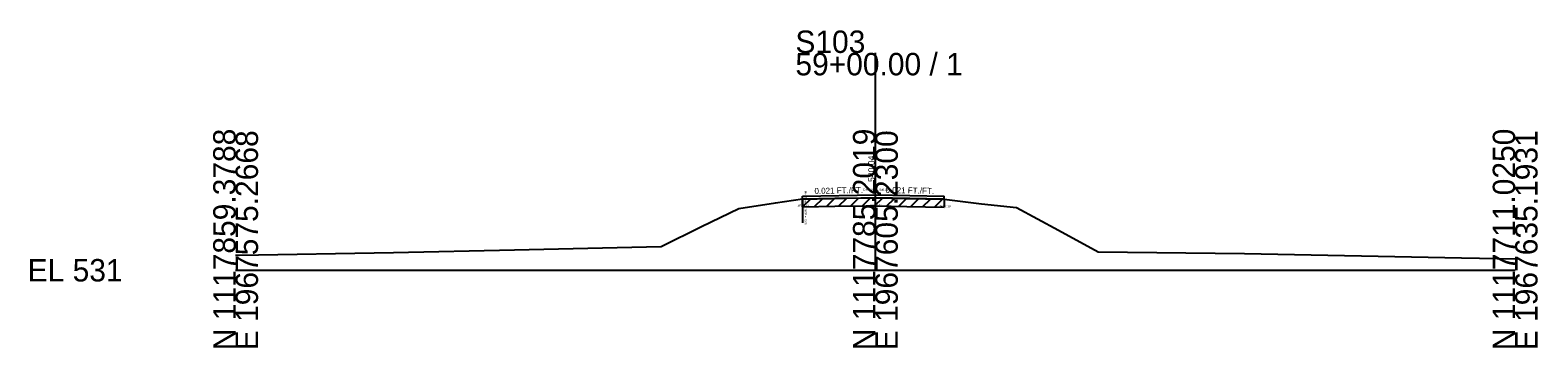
# Model space of a CAD drawing. Extents: x -26 to 163, y -10 to 24018.
# Drawn here: x -25.7 to 162.8, y 8490.3 to 8530 of the extents above; entities that cross this region are included whole.
import ezdxf

# ---------------------------------------------------------------- set-up
doc = ezdxf.new("R2010")
doc.units = 0
for name, color, linetype in [('RD_GPK_XS_Cell', 7, 'Continuous'), ('RD_XS_ExGround', 7, 'Continuous'), ('RD_XS_ExPaveRet', 7, 'Continuous'), ('RD_XS_Misc_Line', 7, 'Continuous'), ('RD_XS_PaveOvlay_CP', 7, 'Continuous'), ('RD_XS_TX_Elev_EX', 7, 'Continuous'), ('RD_XS_TX_ExEOP', 7, 'Continuous'), ('RD_XS_TX_Notes', 7, 'Continuous'), ('RD_XS_TX_Profile', 7, 'Continuous'), ('RD_XS_TX_Slope', 7, 'Continuous')]:
    doc.layers.add(name, color=color, linetype=linetype)

msp = doc.modelspace()

# ---------------------------------------------------------------- linework, layer by layer
at = {"layer": 'RD_GPK_XS_Cell'}
for p, q in [((80, 8500), (80, 8527.15)), ((0, 8500), (80, 8500)), ((80, 8500), (160, 8500))]:
    msp.add_line(p, q, dxfattribs=at)
at = {"layer": 'RD_XS_ExGround'}
msp.add_lwpolyline([(0, 8501.9), (0.46, 8501.89), (19.76, 8502.22), (34.88, 8502.56), (53.2, 8502.97), (58.26, 8505.45), (62.92, 8507.73), (67.49, 8508.44), (70.9, 8508.93), (74.95, 8508.99), (79.28, 8509.05), (80, 8509.04), (83.95, 8508.95), (88.61, 8508.87), (93.26, 8508.31), (97.63, 8507.85), (102.89, 8505), (107.85, 8502.31), (126.16, 8502.09), (153.28, 8501.54), (160, 8501.42)], dxfattribs=at)
at = {"layer": 'RD_XS_ExPaveRet'}
for p, q in [((70.9, 8507.93), (71.92, 8508.94)), ((70.9, 8507.93), (70.9, 8508.93)), ((72.4, 8507.95), (73.42, 8508.97)), ((73.9, 8507.97), (74.92, 8508.99)), ((75.4, 8507.99), (76.42, 8509.01)), ((76.9, 8508.02), (77.92, 8509.03)), ((78.4, 8508.04), (79.41, 8509.05)), ((79.9, 8508.04), (80.88, 8509.02)), ((81.4, 8508), (82.38, 8508.98)), ((82.9, 8507.97), (83.88, 8508.95)), ((84.4, 8507.94), (85.39, 8508.92)), ((85.9, 8507.91), (86.89, 8508.9)), ((87.4, 8507.89), (88.39, 8508.87)), ((88.61, 8508.87), (88.61, 8507.87)), ((70.9, 8507.93), (74.95, 8507.99)), ((74.95, 8507.99), (79.28, 8508.05)), ((79.28, 8508.05), (80, 8508.04)), ((80, 8508.04), (83.95, 8507.95)), ((83.95, 8507.95), (88.61, 8507.87))]:
    msp.add_line(p, q, dxfattribs=at)
at = {"layer": 'RD_XS_Misc_Line'}
msp.add_line((70.9, 8508.93), (70.9, 8505.93), dxfattribs=at)
at = {"layer": 'RD_XS_PaveOvlay_CP'}
for p, q in [((70.9, 8509.25), (80, 8509.44)), ((70.9, 8508.93), (70.9, 8509.25)), ((80, 8509.04), (70.9, 8508.85)), ((80, 8509.44), (88.61, 8509.26)), ((88.61, 8508.86), (80, 8509.04)), ((88.61, 8508.87), (88.61, 8509.26))]:
    msp.add_line(p, q, dxfattribs=at)

# ---------------------------------------------------------------- texts
at = {"layer": 'RD_GPK_XS_Cell'}
for s, p in [('S103', (70, 8527.15)), ('59+00.00 / 1', (70, 8524.35)), ('EL 531', (-26, 8498.6))]:
    msp.add_text(s, height=2.8, dxfattribs=at).set_placement(p)
for s, p in [('N 1117859.3788', (0, 8490)), ('E 1967575.2668', (2.8, 8490)), ('N 1117785.2019', (80, 8490)), ('E 1967605.2300', (82.8, 8490)), ('N 1117711.0250', (160, 8490)), ('E 1967635.1931', (162.8, 8490))]:
    msp.add_text(s, height=2.8, rotation=90, dxfattribs=at).set_placement(p)
at = {"layer": 'RD_XS_TX_Elev_EX'}
msp.add_text('540.04', height=0.8, rotation=90, dxfattribs=at).set_placement((79.9, 8511.04))
at = {"layer": 'RD_XS_TX_ExEOP'}
for s, p in [('EOP-L', (70.85, 8509.25)), ('EOP-R', (88.56, 8509.26))]:
    msp.add_text(s, height=0.1, rotation=270, dxfattribs=at).set_placement(p)
at = {"layer": 'RD_XS_TX_Notes'}
msp.add_text(' Min. Distance @CP = -0.08', height=0.25, rotation=270, dxfattribs=at).set_placement((71.15, 8510.02))
for s, p in [('Elev. @CL = 540.44', (78.47, 8509.94)), (' dE= 0.32', (70.19, 8507.93)), (' dE= 0.40', (79.29, 8508.04)), (' dE= 0.39', (87.9, 8507.87))]:
    msp.add_text(s, height=0.25, dxfattribs=at).set_placement(p)
at = {"layer": 'RD_XS_TX_Profile'}
msp.add_text('CL', height=0.25, dxfattribs=at).set_placement((79.77, 8509.44))
at = {"layer": 'RD_XS_TX_Slope'}
for rotation, p in [(1.1916, (72.39, 8509.53)), (358.8084, (81.26, 8509.66))]:
    msp.add_text('0.021 FT./FT.', height=0.75, rotation=rotation, dxfattribs=at).set_placement(p)

doc.saveas('drawing.dxf')
